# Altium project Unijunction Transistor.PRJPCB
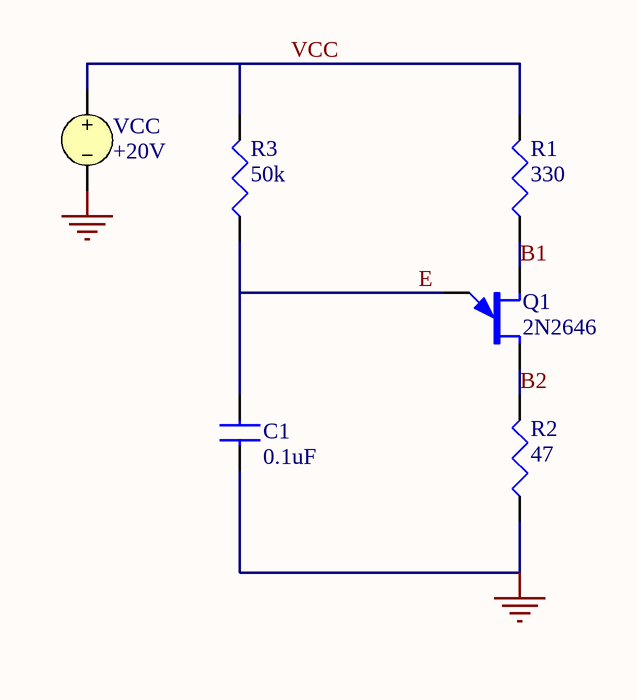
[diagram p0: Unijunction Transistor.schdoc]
1 sheet, 6 parts. Net scope: global (net labels, ports and power ports of the same name join across sheets).

## Sheet Unijunction Transistor.schdoc: Unijunction Transistor
size A4; Organization: Altium Limited; Address1: L3, 12a Rodborough Rd; Address2: Frenchs Forest; Address3: NSW; Address4: Australia 2086; DocumentNumber: 1; SheetNumber: 1; SheetTotal: 1

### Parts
C1  0.1uF
Q1  2N2646
R1  330
R2  47
R3  50k
VCC  +20V

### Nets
GND: C1.2 R2.2(BOT) VCC.2
B1: Q1.1(B2) R1.2(BOT)
B2: Q1.3(B1) R2.1(TOP)
E: C1.1 Q1.2(E) R3.2(BOT)
VCC: R1.1(TOP) R3.1(TOP) VCC.1

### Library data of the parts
C1 = CAP: Capacitor
Q1 = 2N2646: Unijunction Transistor
R1-R3 = RES: Resistor
VCC = VSRC: Voltage Source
